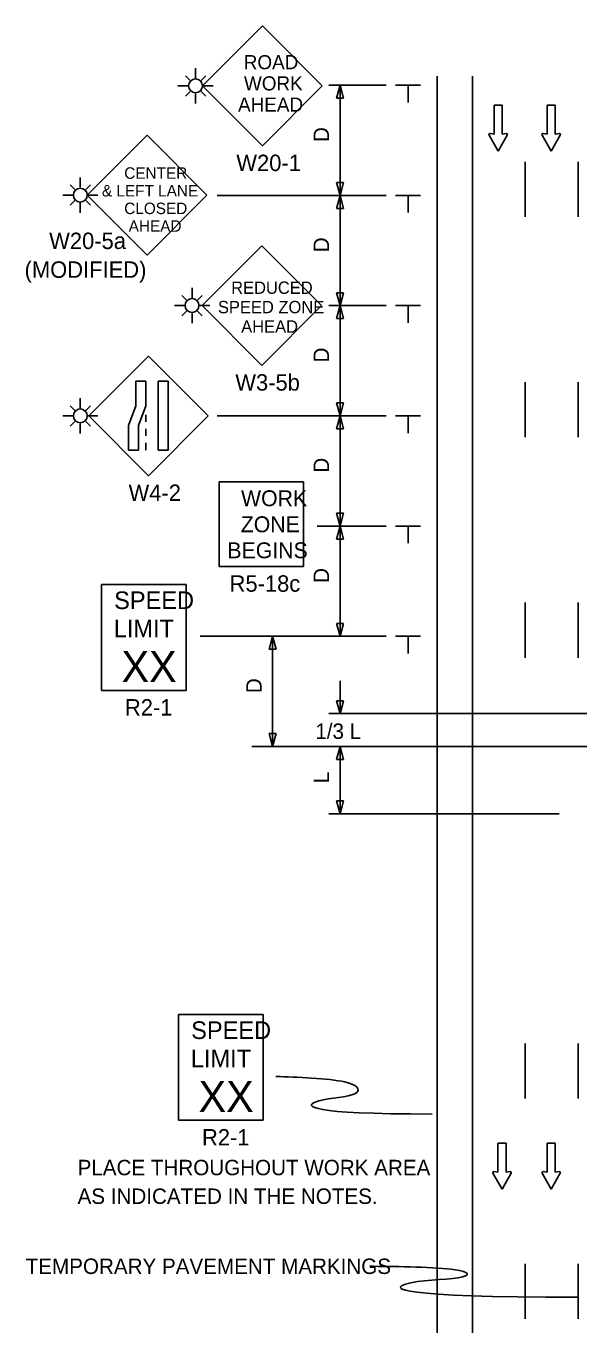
# Model space of a CAD drawing. Extents: x 16544 to 19504, y 5662 to 6909.
# Drawn here: x 16737 to 16987, y 6314 to 6903 of the extents above; entities that cross this region are included whole.
import ezdxf

# ---------------------------------------------------------------- set-up
doc = ezdxf.new("R2010")
doc.units = 0
for name, color, linetype in [('ALI_LEGAL_EX', 7, 'Continuous'), ('MT_SCRATCH_LEVEL_E', 7, 'Continuous'), ('PAVT_EDGE_EX', 7, 'Continuous'), ('TRAFFIC_SIGNS_PR', 7, 'Continuous'), ('TYPICAL_TEXT_DIMEN_PR', 7, 'Continuous')]:
    doc.layers.add(name, color=color, linetype=linetype)

msp = doc.modelspace()

# ---------------------------------------------------------------- linework, layer by layer
at = {"layer": 'ALI_LEGAL_EX'}
for points in [[(16963.46, 6841.23), (16963.46, 6816.23)], [(16987.46, 6841.23), (16987.46, 6816.23)], [(16963.46, 6741.23), (16963.46, 6716.23)], [(16987.46, 6741.23), (16987.46, 6716.23)], [(16987.46, 6741.23), (16987.46, 6716.23)], [(16963.46, 6641.23), (16963.46, 6616.23)], [(16987.46, 6641.23), (16987.46, 6616.23)], [(16987.46, 6641.23), (16987.46, 6616.23)], [(16963.46, 6441.23), (16963.46, 6416.23)], [(16987.46, 6441.23), (16987.46, 6416.23)], [(16987.46, 6441.23), (16987.46, 6416.23)], [(16963.46, 6341.23), (16963.46, 6316.23)], [(16987.46, 6341.23), (16987.46, 6316.23)], [(16987.46, 6341.23), (16987.46, 6316.23)]]:
    msp.add_lwpolyline(points, dxfattribs=at)
at = {"layer": 'MT_SCRATCH_LEVEL_E'}
for p, q in [((16953.06, 6866.95), (16949.32, 6866.95)), ((16949.32, 6866.95), (16949.32, 6853.69)), ((16953.06, 6866.95), (16949.32, 6866.95)), ((16949.32, 6866.95), (16949.32, 6853.69)), ((16953.06, 6853.69), (16953.06, 6866.95)), ((16953.06, 6853.69), (16953.06, 6866.95)), ((16977.13, 6866.95), (16973.39, 6866.95)), ((16973.39, 6866.95), (16973.39, 6853.69)), ((16977.13, 6866.95), (16973.39, 6866.95)), ((16973.39, 6866.95), (16973.39, 6853.69)), ((16977.13, 6853.69), (16977.13, 6866.95)), ((16977.13, 6853.69), (16977.13, 6866.95)), ((16947.06, 6853.32), (16951.21, 6846.09)), ((16947.06, 6853.32), (16951.21, 6846.09)), ((16949.32, 6853.69), (16947.54, 6854.01)), ((16949.32, 6853.69), (16947.54, 6854.01)), ((16951.21, 6846.09), (16955.32, 6853.32)), ((16951.21, 6846.09), (16955.32, 6853.32)), ((16954.83, 6854.01), (16953.06, 6853.69)), ((16954.83, 6854.01), (16953.06, 6853.69)), ((16971.13, 6853.32), (16975.28, 6846.09)), ((16971.13, 6853.32), (16975.28, 6846.09)), ((16973.39, 6853.69), (16971.61, 6854.01)), ((16973.39, 6853.69), (16971.61, 6854.01)), ((16975.28, 6846.09), (16979.39, 6853.32)), ((16975.28, 6846.09), (16979.39, 6853.32)), ((16978.91, 6854.01), (16977.13, 6853.69)), ((16978.91, 6854.01), (16977.13, 6853.69)), ((16954.79, 6396.02), (16951.05, 6396.02)), ((16951.05, 6396.02), (16951.05, 6382.76)), ((16954.79, 6396.02), (16951.05, 6396.02)), ((16951.05, 6396.02), (16951.05, 6382.76)), ((16954.79, 6382.76), (16954.79, 6396.02)), ((16954.79, 6382.76), (16954.79, 6396.02)), ((16977.13, 6396.02), (16973.39, 6396.02)), ((16973.39, 6396.02), (16973.39, 6382.76)), ((16977.13, 6396.02), (16973.39, 6396.02)), ((16973.39, 6396.02), (16973.39, 6382.76)), ((16977.13, 6382.76), (16977.13, 6396.02)), ((16977.13, 6382.76), (16977.13, 6396.02)), ((16948.79, 6382.39), (16952.94, 6375.15)), ((16948.79, 6382.39), (16952.94, 6375.15)), ((16951.05, 6382.76), (16949.27, 6383.08)), ((16951.05, 6382.76), (16949.27, 6383.08)), ((16952.94, 6375.15), (16957.05, 6382.39)), ((16952.94, 6375.15), (16957.05, 6382.39)), ((16956.57, 6383.08), (16954.79, 6382.76)), ((16956.57, 6383.08), (16954.79, 6382.76)), ((16971.13, 6382.39), (16975.28, 6375.15)), ((16971.13, 6382.39), (16975.28, 6375.15)), ((16973.39, 6382.76), (16971.61, 6383.08)), ((16973.39, 6382.76), (16971.61, 6383.08)), ((16975.28, 6375.15), (16979.39, 6382.39)), ((16975.28, 6375.15), (16979.39, 6382.39)), ((16978.91, 6383.08), (16977.13, 6382.76)), ((16978.91, 6383.08), (16977.13, 6382.76))]:
    msp.add_line(p, q, dxfattribs=at)
for centre, start, end in [((16947.47, 6853.55), 80.03619, 209.77312), ((16947.47, 6853.55), 80.03619, 209.77312), ((16954.91, 6853.55), 330.42484, 99.96381), ((16954.91, 6853.55), 330.42484, 99.96381), ((16971.54, 6853.55), 80.03619, 209.77312), ((16971.54, 6853.55), 80.03619, 209.77312), ((16978.98, 6853.55), 330.42484, 99.96381), ((16978.98, 6853.55), 330.42484, 99.96381), ((16949.2, 6382.62), 80.03619, 209.77312), ((16949.2, 6382.62), 80.03619, 209.77312), ((16956.64, 6382.62), 330.42484, 99.96381), ((16956.64, 6382.62), 330.42484, 99.96381), ((16971.54, 6382.62), 80.03619, 209.77312), ((16971.54, 6382.62), 80.03619, 209.77312), ((16978.98, 6382.62), 330.42484, 99.96381), ((16978.98, 6382.62), 330.42484, 99.96381)]:
    msp.add_arc(centre, 0.463, start, end, dxfattribs=at)
at = {"layer": 'PAVT_EDGE_EX'}
for p, q in [((16923.46, 6880.02), (16923.46, 6106.05)), ((16939.46, 6880.02), (16939.46, 6106.05))]:
    msp.add_line(p, q, dxfattribs=at)
at = {"layer": 'TRAFFIC_SIGNS_PR'}
for p, q in [((16844.12, 6902.82), (16816.94, 6875.63)), ((16871.31, 6875.63), (16844.12, 6902.82)), ((16811.27, 6878.15), (16809.16, 6880.25)), ((16813.78, 6879.19), (16813.78, 6883.69)), ((16816.3, 6878.15), (16818.41, 6880.25)), ((16810.63, 6875.63), (16805.79, 6875.63)), ((16811.27, 6873.12), (16809.16, 6871.01)), ((16816.3, 6873.12), (16818.4, 6871.01)), ((16816.94, 6875.63), (16821.82, 6875.63)), ((16816.94, 6875.63), (16844.12, 6848.45)), ((16844.12, 6848.45), (16871.31, 6875.63)), ((16813.78, 6867.67), (16813.78, 6872.08)), ((16791.76, 6853.27), (16764.57, 6826.08)), ((16818.95, 6826.08), (16791.76, 6853.27)), ((16761.42, 6829.63), (16761.42, 6834.14)), ((16758.26, 6826.08), (16753.43, 6826.08)), ((16758.91, 6828.59), (16756.8, 6830.7)), ((16763.93, 6828.59), (16766.04, 6830.7)), ((16764.57, 6826.08), (16769.45, 6826.08)), ((16764.57, 6826.08), (16791.76, 6798.89)), ((16791.76, 6798.89), (16818.95, 6826.08)), ((16758.9, 6823.57), (16756.8, 6821.46)), ((16761.42, 6818.11), (16761.42, 6822.52)), ((16763.93, 6823.57), (16766.04, 6821.46)), ((16843.88, 6803.13), (16816.72, 6775.98)), ((16871.03, 6775.98), (16843.88, 6803.13)), ((16812.17, 6779.53), (16812.17, 6784.03)), ((16809.66, 6778.49), (16807.55, 6780.6)), ((16814.68, 6778.49), (16816.79, 6780.6)), ((16809.02, 6775.98), (16804.18, 6775.98)), ((16809.66, 6773.46), (16807.55, 6771.36)), ((16812.17, 6768.01), (16812.17, 6772.42)), ((16814.68, 6773.46), (16816.79, 6771.36)), ((16815.33, 6775.98), (16820.21, 6775.98)), ((16816.72, 6775.98), (16843.88, 6748.83)), ((16843.88, 6748.83), (16871.03, 6775.98)), ((16792.41, 6753.09), (16765.25, 6725.94)), ((16819.56, 6725.94), (16792.41, 6753.09)), ((16761.42, 6729.46), (16761.42, 6733.96)), ((16758.26, 6725.91), (16753.43, 6725.91)), ((16758.9, 6728.42), (16756.8, 6730.53)), ((16763.93, 6728.42), (16766.04, 6730.53)), ((16764.57, 6725.91), (16769.45, 6725.91)), ((16765.25, 6725.94), (16792.41, 6698.78)), ((16791.16, 6726.43), (16791.16, 6723.23)), ((16792.41, 6698.78), (16819.56, 6725.94)), ((16758.9, 6723.39), (16756.8, 6721.28)), ((16761.42, 6717.94), (16761.42, 6722.35)), ((16763.93, 6723.39), (16766.04, 6721.29)), ((16791.16, 6720.03), (16791.16, 6716.83)), ((16791.16, 6713.63), (16791.16, 6710.43)), ((16824.42, 6657.58), (16824.42, 6695.98)), ((16824.42, 6695.98), (16862.82, 6695.98)), ((16862.82, 6657.58), (16862.82, 6695.98)), ((16824.42, 6657.58), (16862.82, 6657.58)), ((16771.03, 6649.42), (16809.43, 6649.42)), ((16771.03, 6601.42), (16771.03, 6649.42)), ((16809.43, 6601.42), (16809.43, 6649.42)), ((16771.03, 6601.42), (16809.43, 6601.42)), ((16806.02, 6454.39), (16844.42, 6454.39)), ((16806.02, 6406.39), (16806.02, 6454.39)), ((16844.42, 6406.39), (16844.42, 6454.39)), ((16806.02, 6406.39), (16844.42, 6406.39))]:
    msp.add_line(p, q, dxfattribs=at)
for points in [[(16791.16, 6741.67), (16791.16, 6730.49), (16787.81, 6721.61), (16787.81, 6710.43), (16783.32, 6710.43), (16783.32, 6721.61), (16786.66, 6730.49), (16786.66, 6741.67)], [(16801.29, 6741.67), (16801.29, 6710.43), (16796.8, 6710.43), (16796.8, 6741.67)]]:
    msp.add_lwpolyline(points, close=True, dxfattribs=at)
for centre in [(16813.78, 6875.63), (16761.42, 6826.08), (16812.17, 6775.98), (16761.42, 6725.91)]:
    msp.add_circle(centre, 3.15, dxfattribs=at)
at = {"layer": 'TYPICAL_TEXT_DIMEN_PR'}
for p, q in [((16874.36, 6875.93), (16900.36, 6875.93)), ((16877.79, 6870.07), (16879.36, 6875.93)), ((16879.36, 6825.93), (16879.36, 6875.93)), ((16879.36, 6875.93), (16880.93, 6870.07)), ((16904.61, 6875.93), (16915.86, 6875.93)), ((16910.24, 6875.93), (16910.24, 6868.15)), ((16879.36, 6870.07), (16877.79, 6870.07)), ((16880.93, 6870.07), (16879.36, 6870.07)), ((16879.36, 6825.93), (16877.79, 6831.79)), ((16877.79, 6831.79), (16879.36, 6831.79)), ((16879.36, 6831.79), (16880.93, 6831.79)), ((16880.93, 6831.79), (16879.36, 6825.93)), ((16823.56, 6825.93), (16900.36, 6825.93)), ((16874.36, 6825.93), (16900.36, 6825.93)), ((16877.79, 6820.07), (16879.36, 6825.93)), ((16879.36, 6775.93), (16879.36, 6825.93)), ((16879.36, 6825.93), (16880.93, 6820.07)), ((16904.61, 6825.93), (16915.86, 6825.93)), ((16910.24, 6825.93), (16910.24, 6818.15)), ((16879.36, 6820.07), (16877.79, 6820.07)), ((16880.93, 6820.07), (16879.36, 6820.07)), ((16879.36, 6775.93), (16877.79, 6781.79)), ((16877.79, 6781.79), (16879.36, 6781.79)), ((16879.36, 6781.79), (16880.93, 6781.79)), ((16880.93, 6781.79), (16879.36, 6775.93)), ((16874.36, 6775.93), (16900.36, 6775.93)), ((16874.36, 6775.93), (16900.36, 6775.93)), ((16877.79, 6770.07), (16879.36, 6775.93)), ((16879.36, 6775.93), (16880.93, 6770.07)), ((16879.36, 6725.93), (16879.36, 6775.93)), ((16904.61, 6775.93), (16915.86, 6775.93)), ((16910.24, 6775.93), (16910.24, 6768.15)), ((16879.36, 6770.07), (16877.79, 6770.07)), ((16880.93, 6770.07), (16879.36, 6770.07)), ((16879.36, 6725.93), (16877.79, 6731.79)), ((16877.79, 6731.79), (16879.36, 6731.79)), ((16879.36, 6731.79), (16880.93, 6731.79)), ((16880.93, 6731.79), (16879.36, 6725.93)), ((16823.56, 6725.93), (16900.36, 6725.93)), ((16877.79, 6720.07), (16879.36, 6725.93)), ((16877.79, 6720.07), (16879.36, 6725.93)), ((16879.36, 6725.93), (16880.93, 6720.07)), ((16879.36, 6675.93), (16879.36, 6725.93)), ((16879.36, 6725.93), (16880.93, 6720.07)), ((16904.61, 6725.93), (16915.86, 6725.93)), ((16910.24, 6725.93), (16910.24, 6718.15)), ((16879.36, 6720.07), (16877.79, 6720.07)), ((16879.36, 6720.07), (16877.79, 6720.07)), ((16880.93, 6720.07), (16879.36, 6720.07)), ((16880.93, 6720.07), (16879.36, 6720.07)), ((16879.36, 6675.93), (16877.79, 6681.79)), ((16877.79, 6681.79), (16879.36, 6681.79)), ((16879.36, 6681.79), (16880.93, 6681.79)), ((16880.93, 6681.79), (16879.36, 6675.93)), ((16869.06, 6675.93), (16900.36, 6675.93)), ((16874.36, 6675.93), (16900.36, 6675.93)), ((16877.79, 6670.07), (16879.36, 6675.93)), ((16879.36, 6625.93), (16879.36, 6675.93)), ((16879.36, 6675.93), (16880.93, 6670.07)), ((16904.61, 6675.93), (16915.86, 6675.93)), ((16910.24, 6675.93), (16910.24, 6668.15)), ((16879.36, 6670.07), (16877.79, 6670.07)), ((16880.93, 6670.07), (16879.36, 6670.07)), ((16879.36, 6625.93), (16877.79, 6631.79)), ((16877.79, 6631.79), (16879.36, 6631.79)), ((16879.36, 6631.79), (16880.93, 6631.79)), ((16880.93, 6631.79), (16879.36, 6625.93)), ((16815.93, 6625.93), (16900.36, 6625.93)), ((16847.21, 6620.07), (16848.78, 6625.93)), ((16848.78, 6625.93), (16850.35, 6620.07)), ((16848.78, 6575.93), (16848.78, 6625.93)), ((16904.61, 6625.93), (16915.86, 6625.93)), ((16910.24, 6625.93), (16910.24, 6618.15)), ((16848.78, 6620.07), (16847.21, 6620.07)), ((16850.35, 6620.07), (16848.78, 6620.07)), ((16879.36, 6605.78), (16879.36, 6590.85)), ((16879.36, 6590.85), (16877.79, 6596.72)), ((16877.79, 6596.72), (16879.36, 6596.72)), ((16879.36, 6596.72), (16880.93, 6596.72)), ((16880.93, 6596.72), (16879.36, 6590.85)), ((16874.36, 6590.85), (17023.87, 6590.85)), ((16848.78, 6575.93), (16847.21, 6581.79)), ((16847.21, 6581.79), (16848.78, 6581.79)), ((16848.78, 6581.79), (16850.35, 6581.79)), ((16850.35, 6581.79), (16848.78, 6575.93)), ((16980.27, 6575.93), (16839.26, 6575.93)), ((17000.44, 6575.93), (16848.78, 6575.93)), ((16877.79, 6570.07), (16879.36, 6575.93)), ((16879.36, 6545.4), (16879.36, 6575.93)), ((16879.36, 6575.93), (16880.93, 6570.07)), ((16879.36, 6570.07), (16877.79, 6570.07)), ((16880.93, 6570.07), (16879.36, 6570.07)), ((16879.36, 6545.4), (16877.79, 6551.26)), ((16877.79, 6551.26), (16879.36, 6551.26)), ((16879.36, 6551.26), (16880.93, 6551.26)), ((16880.93, 6551.26), (16879.36, 6545.4)), ((16874.36, 6545.4), (16978.94, 6545.4))]:
    msp.add_line(p, q, dxfattribs=at)
for points in [[(16921.26, 6409.18), (16863.81, 6409.18), (16863.81, 6416.45), (16888.98, 6416.45), (16888.98, 6424.87), (16859.21, 6426.02), (16850.26, 6426.2)], [(16987.87, 6326.11), (16903.1, 6326.11), (16903.1, 6333.99), (16939.05, 6333.99), (16939.05, 6339.64), (16901.89, 6340.08), (16892.9, 6340.13)]]:
    msp.add_open_spline(points, degree=3, dxfattribs=at)

# ---------------------------------------------------------------- texts
at = {"layer": 'TRAFFIC_SIGNS_PR'}
for s, height, p in [('ROAD', 6.408, (16835.66, 6883.18)), ('WORK', 6.408, (16835.76, 6873.57)), ('AHEAD', 6.408, (16833.07, 6863.95)), ('W20-1', 7.449, (16832.28, 6836.99)), ('CENTER', 5.206, (16781.38, 6833.49)), ('& LEFT LANE', 5.2065, (16771.24, 6825.48)), ('CLOSED', 5.206, (16781.38, 6817.47)), ('AHEAD', 5.206, (16783.41, 6809.46)), ('W20-5a', 7.449, (16747.29, 6801.62)), ('(MODIFIED)', 7.449, (16736.13, 6788.57)), ('REDUCED', 5.6, (16829.93, 6781.29)), ('SPEED ZONE', 5.6, (16823.92, 6772.49)), ('AHEAD', 5.6, (16834.49, 6763.69)), ('W3-5b', 7.44, (16831.83, 6737.39)), ('W4-2', 7.44, (16783.36, 6687.35)), ('WORK', 7.217, (16834.42, 6684.95)), ('ZONE', 7.217, (16834.3, 6673.14)), ('BEGINS', 7.217, (16828.23, 6661.33)), ('R5-18c', 7.44, (16829.23, 6646.15)), ('SPEED', 8, (16776.8, 6638.28)), ('LIMIT', 8, (16776.64, 6625.48)), ('XX', 14.031, (16780.15, 6605.17)), ('R2-1', 7.44, (16781.71, 6589.98)), ('SPEED', 8, (16811.79, 6443.25)), ('LIMIT', 8, (16811.63, 6430.45)), ('XX', 14.031, (16815.13, 6410.14)), ('R2-1', 7.44, (16816.7, 6394.95)), ('PLACE THROUGHOUT WORK AREA', 7, (16760.19, 6381.43)), ('AS INDICATED IN THE NOTES.', 7, (16760.19, 6368.43)), ('TEMPORARY PAVEMENT MARKINGS', 7, (16736.63, 6336.64))]:
    msp.add_text(s, height=height, dxfattribs=at).set_placement(p)
at = {"layer": 'TYPICAL_TEXT_DIMEN_PR'}
for s, p in [('D', (16874.36, 6850.15)), ('D', (16874.36, 6800.15)), ('D', (16874.36, 6750.15)), ('D', (16874.36, 6700.15)), ('D', (16874.36, 6700.15)), ('D', (16874.36, 6650.15)), ('D', (16843.78, 6600.15)), ('L', (16874.36, 6559.26))]:
    msp.add_text(s, height=7, rotation=90, dxfattribs=at).set_placement(p)
msp.add_text('1/3 L', height=7, dxfattribs=at).set_placement((16868.15, 6579.38))

doc.saveas('drawing.dxf')
